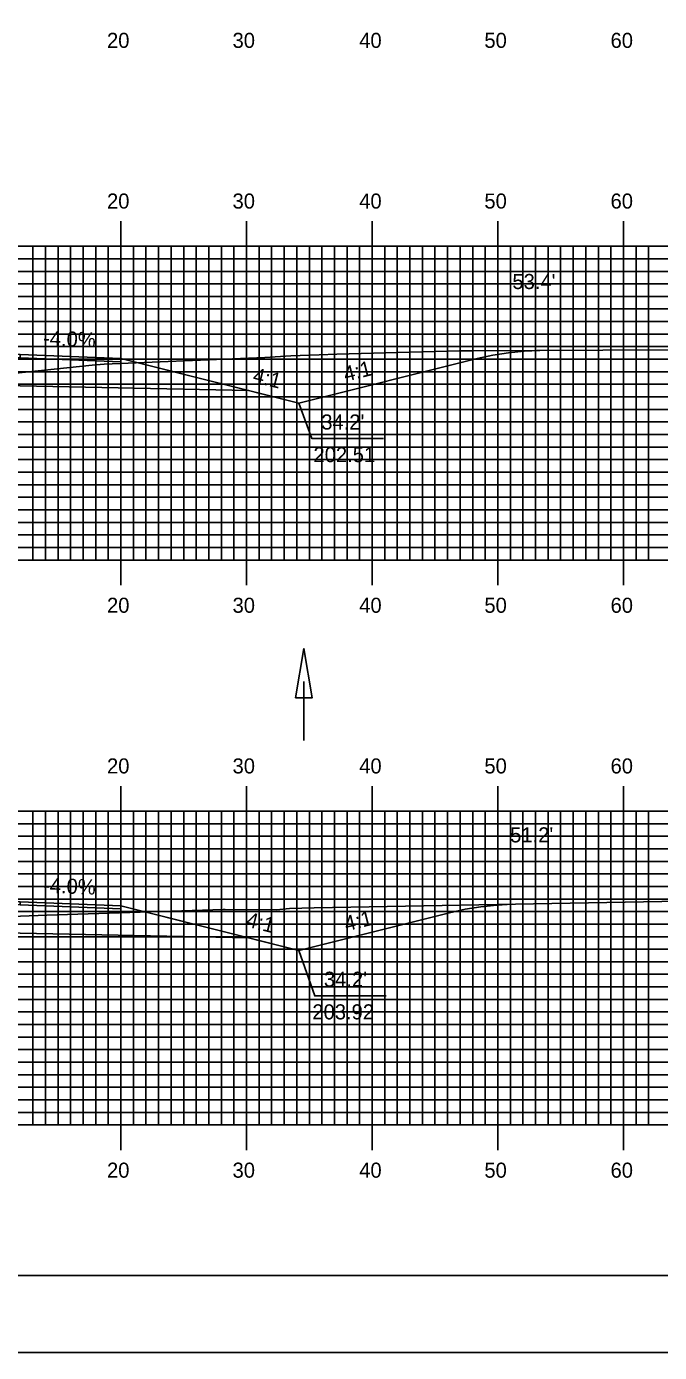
# Model space of a CAD drawing. Extents: x 1821998 to 1822342, y 442591 to 442811.
# Drawn here: x 1822176.8 to 1822227.1, y 442590.5 to 442696.2 of the extents above; entities that cross this region are included whole.
import ezdxf

# ---------------------------------------------------------------- set-up
doc = ezdxf.new("R2010")
doc.units = 0
for name, color, linetype in [('ANNOTATION', 7, 'Continuous'), ('BORDER', 7, 'Continuous'), ('D_Drainage_Ditch_Line', 7, 'Continuous'), ('D_Roadway_Centerline', 7, 'Continuous'), ('D_Roadway_Edge_Shoulder', 7, 'Continuous'), ('D_Roadway_SlopeLines', 7, 'Continuous'), ('D_Roadway_SubGrade', 7, 'Continuous'), ('D_Text_Standard', 7, 'Continuous'), ('H_V ANNOTATION', 7, 'Continuous'), ('MAJOR', 7, 'Continuous'), ('MINOR', 7, 'Continuous'), ('PLOT BOUNDARY', 7, 'Continuous'), ('S_Roadway_Centerline', 7, 'Continuous')]:
    doc.layers.add(name, color=color, linetype=linetype)

msp = doc.modelspace()

# ---------------------------------------------------------------- linework, layer by layer
at = {"layer": 'ANNOTATION'}
for points in [[(1822205.16, 442663.35), (1822199.47, 442663.35), (1822198.43, 442666.18)], [(1822205.38, 442618.95), (1822199.69, 442618.95), (1822198.43, 442622.58)]]:
    msp.add_lwpolyline(points, dxfattribs=at)
at = {"layer": 'BORDER'}
msp.add_lwpolyline([(1822014.66, 442596.67), (1822334.66, 442596.67), (1822334.66, 442806.67), (1822014.66, 442806.67)], close=True, dxfattribs=at)
at = {"layer": 'D_Drainage_Ditch_Line'}
msp.add_line((1822198.83, 442644), (1822198.83, 442639.3), dxfattribs=at)
msp.add_lwpolyline([(1822198.17, 442642.69), (1822199.48, 442642.69), (1822198.83, 442646.62)], close=True, dxfattribs=at)
at = {"layer": 'D_Roadway_Centerline'}
for points in [[(1822116.01, 442664.99), (1822122.31, 442666.56), (1822123.97, 442666.97), (1822134.31, 442669.56), (1822140.32, 442669.8), (1822164.26, 442670.28), (1822176.26, 442670.04), (1822184.26, 442669.72), (1822194.43, 442667.18), (1822198.43, 442666.18), (1822212.61, 442669.72), (1822213.86, 442669.99), (1822215.11, 442670.19), (1822216.36, 442670.31), (1822217.61, 442670.36)], [(1822113.09, 442620.68), (1822122.26, 442622.97), (1822123.91, 442623.38), (1822134.26, 442625.97), (1822140.26, 442626.21), (1822164.26, 442626.69), (1822176.26, 442626.45), (1822184.26, 442626.13), (1822194.43, 442623.58), (1822198.43, 442622.58), (1822210.42, 442625.58), (1822211.67, 442625.86), (1822212.92, 442626.06), (1822214.17, 442626.19), (1822215.42, 442626.25)]]:
    msp.add_lwpolyline(points, dxfattribs=at)
at = {"layer": 'D_Roadway_Edge_Shoulder'}
for points in [[(1822176.26, 442670.04), (1822184.26, 442669.72), (1822184.26, 442669.47), (1822176.26, 442669.79)], [(1822176.26, 442626.45), (1822184.26, 442626.13), (1822184.26, 442625.88), (1822176.26, 442626.2)]]:
    msp.add_lwpolyline(points, close=True, dxfattribs=at)
at = {"layer": 'D_Roadway_SlopeLines'}
for points in [[(1822198.43, 442666.18), (1822212.61, 442669.72), (1822213.86, 442669.99), (1822215.11, 442670.19), (1822216.36, 442670.31), (1822217.61, 442670.36)], [(1822184.26, 442669.72), (1822198.43, 442666.18)], [(1822184.26, 442626.13), (1822198.43, 442622.58)], [(1822198.43, 442622.58), (1822210.42, 442625.58), (1822211.67, 442625.86), (1822212.92, 442626.06), (1822214.17, 442626.19), (1822215.42, 442626.25)]]:
    msp.add_lwpolyline(points, dxfattribs=at)
at = {"layer": 'D_Roadway_SubGrade'}
for points in [[(1822140.32, 442667.3), (1822123.97, 442666.97), (1822134.31, 442669.56), (1822134.31, 442669.31), (1822140.32, 442669.55), (1822164.26, 442670.03), (1822176.26, 442669.79), (1822184.26, 442669.47), (1822184.26, 442669.72), (1822194.43, 442667.18), (1822176.26, 442667.54), (1822164.26, 442667.78)], [(1822140.26, 442623.71), (1822123.91, 442623.38), (1822134.26, 442625.97), (1822134.26, 442625.72), (1822140.26, 442625.96), (1822164.26, 442626.44), (1822176.26, 442626.2), (1822184.26, 442625.88), (1822184.26, 442626.13), (1822194.43, 442623.58), (1822176.26, 442623.95), (1822164.26, 442624.19)]]:
    msp.add_lwpolyline(points, close=True, dxfattribs=at)
at = {"layer": 'MAJOR'}
for p, q in [((1822184.26, 442680.67), (1822184.26, 442678.67)), ((1822194.26, 442680.67), (1822194.26, 442678.67)), ((1822204.26, 442680.67), (1822204.26, 442678.67)), ((1822214.26, 442680.67), (1822214.26, 442678.67)), ((1822224.26, 442680.67), (1822224.26, 442678.67)), ((1822024.26, 442678.67), (1822304.26, 442678.67)), ((1822024.26, 442678.67), (1822304.26, 442678.67)), ((1822184.26, 442653.67), (1822184.26, 442678.67)), ((1822194.26, 442653.67), (1822194.26, 442678.67)), ((1822204.26, 442653.67), (1822204.26, 442678.67)), ((1822214.26, 442653.67), (1822214.26, 442678.67)), ((1822224.26, 442653.67), (1822224.26, 442678.67)), ((1822024.26, 442673.67), (1822304.26, 442673.67)), ((1822024.26, 442668.67), (1822304.26, 442668.67)), ((1822024.26, 442663.67), (1822304.26, 442663.67)), ((1822024.26, 442658.67), (1822304.26, 442658.67)), ((1822024.26, 442653.67), (1822304.26, 442653.67)), ((1822024.26, 442653.67), (1822304.26, 442653.67)), ((1822184.26, 442651.66), (1822184.26, 442653.67)), ((1822194.26, 442651.66), (1822194.26, 442653.67)), ((1822204.26, 442651.66), (1822204.26, 442653.67)), ((1822214.26, 442651.66), (1822214.26, 442653.67)), ((1822224.26, 442651.66), (1822224.26, 442653.67)), ((1822184.26, 442635.67), (1822184.26, 442633.67)), ((1822194.26, 442635.67), (1822194.26, 442633.67)), ((1822204.26, 442635.67), (1822204.26, 442633.67)), ((1822214.26, 442635.67), (1822214.26, 442633.67)), ((1822224.26, 442635.67), (1822224.26, 442633.67)), ((1822024.26, 442633.67), (1822304.26, 442633.67)), ((1822024.26, 442633.67), (1822304.26, 442633.67)), ((1822184.26, 442608.67), (1822184.26, 442633.67)), ((1822194.26, 442608.67), (1822194.26, 442633.67)), ((1822204.26, 442608.67), (1822204.26, 442633.67)), ((1822214.26, 442608.67), (1822214.26, 442633.67)), ((1822224.26, 442608.67), (1822224.26, 442633.67)), ((1822024.26, 442628.67), (1822304.26, 442628.67)), ((1822024.26, 442623.67), (1822304.26, 442623.67)), ((1822024.26, 442618.67), (1822304.26, 442618.67)), ((1822024.26, 442613.67), (1822304.26, 442613.67)), ((1822024.26, 442608.67), (1822304.26, 442608.67)), ((1822024.26, 442608.67), (1822304.26, 442608.67)), ((1822184.26, 442606.66), (1822184.26, 442608.67)), ((1822194.26, 442606.66), (1822194.26, 442608.67)), ((1822204.26, 442606.66), (1822204.26, 442608.67)), ((1822214.26, 442606.66), (1822214.26, 442608.67)), ((1822224.26, 442606.66), (1822224.26, 442608.67))]:
    msp.add_line(p, q, dxfattribs=at)
at = {"layer": 'MINOR'}
for p, q in [((1822177.26, 442653.67), (1822177.26, 442678.67)), ((1822178.26, 442653.67), (1822178.26, 442678.67)), ((1822179.26, 442653.67), (1822179.26, 442678.67)), ((1822180.26, 442653.67), (1822180.26, 442678.67)), ((1822181.26, 442653.67), (1822181.26, 442678.67)), ((1822182.26, 442653.67), (1822182.26, 442678.67)), ((1822183.26, 442653.67), (1822183.26, 442678.67)), ((1822185.26, 442653.67), (1822185.26, 442678.67)), ((1822186.26, 442653.67), (1822186.26, 442678.67)), ((1822187.26, 442653.67), (1822187.26, 442678.67)), ((1822188.26, 442653.67), (1822188.26, 442678.67)), ((1822189.26, 442653.67), (1822189.26, 442678.67)), ((1822190.26, 442653.67), (1822190.26, 442678.67)), ((1822191.26, 442653.67), (1822191.26, 442678.67)), ((1822192.26, 442653.67), (1822192.26, 442678.67)), ((1822193.26, 442653.67), (1822193.26, 442678.67)), ((1822195.26, 442653.67), (1822195.26, 442678.67)), ((1822196.26, 442653.67), (1822196.26, 442678.67)), ((1822197.26, 442653.67), (1822197.26, 442678.67)), ((1822198.26, 442653.67), (1822198.26, 442678.67)), ((1822199.26, 442653.67), (1822199.26, 442678.67)), ((1822200.26, 442653.67), (1822200.26, 442678.67)), ((1822201.26, 442653.67), (1822201.26, 442678.67)), ((1822202.26, 442653.67), (1822202.26, 442678.67)), ((1822203.26, 442653.67), (1822203.26, 442678.67)), ((1822205.26, 442653.67), (1822205.26, 442678.67)), ((1822206.26, 442653.67), (1822206.26, 442678.67)), ((1822207.26, 442653.67), (1822207.26, 442678.67)), ((1822208.26, 442653.67), (1822208.26, 442678.67)), ((1822209.26, 442653.67), (1822209.26, 442678.67)), ((1822210.26, 442653.67), (1822210.26, 442678.67)), ((1822211.26, 442653.67), (1822211.26, 442678.67)), ((1822212.26, 442653.67), (1822212.26, 442678.67)), ((1822213.26, 442653.67), (1822213.26, 442678.67)), ((1822215.26, 442653.67), (1822215.26, 442678.67)), ((1822216.26, 442653.67), (1822216.26, 442678.67)), ((1822217.26, 442653.67), (1822217.26, 442678.67)), ((1822218.26, 442653.67), (1822218.26, 442678.67)), ((1822219.26, 442653.67), (1822219.26, 442678.67)), ((1822220.26, 442653.67), (1822220.26, 442678.67)), ((1822221.26, 442653.67), (1822221.26, 442678.67)), ((1822222.26, 442653.67), (1822222.26, 442678.67)), ((1822223.26, 442653.67), (1822223.26, 442678.67)), ((1822225.26, 442653.67), (1822225.26, 442678.67)), ((1822226.26, 442653.67), (1822226.26, 442678.67)), ((1822024.26, 442677.67), (1822304.26, 442677.67)), ((1822024.26, 442676.67), (1822304.26, 442676.67)), ((1822024.26, 442675.67), (1822304.26, 442675.67)), ((1822024.26, 442674.67), (1822304.26, 442674.67)), ((1822024.26, 442672.67), (1822304.26, 442672.67)), ((1822024.26, 442671.67), (1822304.26, 442671.67)), ((1822024.26, 442670.67), (1822304.26, 442670.67)), ((1822024.26, 442669.67), (1822304.26, 442669.67)), ((1822024.26, 442667.67), (1822304.26, 442667.67)), ((1822024.26, 442666.67), (1822304.26, 442666.67)), ((1822024.26, 442665.67), (1822304.26, 442665.67)), ((1822024.26, 442664.67), (1822304.26, 442664.67)), ((1822024.26, 442662.67), (1822304.26, 442662.67)), ((1822024.26, 442661.67), (1822304.26, 442661.67)), ((1822024.26, 442660.67), (1822304.26, 442660.67)), ((1822024.26, 442659.67), (1822304.26, 442659.67)), ((1822024.26, 442657.67), (1822304.26, 442657.67)), ((1822024.26, 442656.67), (1822304.26, 442656.67)), ((1822024.26, 442655.67), (1822304.26, 442655.67)), ((1822024.26, 442654.67), (1822304.26, 442654.67)), ((1822177.26, 442608.67), (1822177.26, 442633.67)), ((1822178.26, 442608.67), (1822178.26, 442633.67)), ((1822179.26, 442608.67), (1822179.26, 442633.67)), ((1822180.26, 442608.67), (1822180.26, 442633.67)), ((1822181.26, 442608.67), (1822181.26, 442633.67)), ((1822182.26, 442608.67), (1822182.26, 442633.67)), ((1822183.26, 442608.67), (1822183.26, 442633.67)), ((1822185.26, 442608.67), (1822185.26, 442633.67)), ((1822186.26, 442608.67), (1822186.26, 442633.67)), ((1822187.26, 442608.67), (1822187.26, 442633.67)), ((1822188.26, 442608.67), (1822188.26, 442633.67)), ((1822189.26, 442608.67), (1822189.26, 442633.67)), ((1822190.26, 442608.67), (1822190.26, 442633.67)), ((1822191.26, 442608.67), (1822191.26, 442633.67)), ((1822192.26, 442608.67), (1822192.26, 442633.67)), ((1822193.26, 442608.67), (1822193.26, 442633.67)), ((1822195.26, 442608.67), (1822195.26, 442633.67)), ((1822196.26, 442608.67), (1822196.26, 442633.67)), ((1822197.26, 442608.67), (1822197.26, 442633.67)), ((1822198.26, 442608.67), (1822198.26, 442633.67)), ((1822199.26, 442608.67), (1822199.26, 442633.67)), ((1822200.26, 442608.67), (1822200.26, 442633.67)), ((1822201.26, 442608.67), (1822201.26, 442633.67)), ((1822202.26, 442608.67), (1822202.26, 442633.67)), ((1822203.26, 442608.67), (1822203.26, 442633.67)), ((1822205.26, 442608.67), (1822205.26, 442633.67)), ((1822206.26, 442608.67), (1822206.26, 442633.67)), ((1822207.26, 442608.67), (1822207.26, 442633.67)), ((1822208.26, 442608.67), (1822208.26, 442633.67)), ((1822209.26, 442608.67), (1822209.26, 442633.67)), ((1822210.26, 442608.67), (1822210.26, 442633.67)), ((1822211.26, 442608.67), (1822211.26, 442633.67)), ((1822212.26, 442608.67), (1822212.26, 442633.67)), ((1822213.26, 442608.67), (1822213.26, 442633.67)), ((1822215.26, 442608.67), (1822215.26, 442633.67)), ((1822216.26, 442608.67), (1822216.26, 442633.67)), ((1822217.26, 442608.67), (1822217.26, 442633.67)), ((1822218.26, 442608.67), (1822218.26, 442633.67)), ((1822219.26, 442608.67), (1822219.26, 442633.67)), ((1822220.26, 442608.67), (1822220.26, 442633.67)), ((1822221.26, 442608.67), (1822221.26, 442633.67)), ((1822222.26, 442608.67), (1822222.26, 442633.67)), ((1822223.26, 442608.67), (1822223.26, 442633.67)), ((1822225.26, 442608.67), (1822225.26, 442633.67)), ((1822226.26, 442608.67), (1822226.26, 442633.67)), ((1822024.26, 442632.67), (1822304.26, 442632.67)), ((1822024.26, 442631.67), (1822304.26, 442631.67)), ((1822024.26, 442630.67), (1822304.26, 442630.67)), ((1822024.26, 442629.67), (1822304.26, 442629.67)), ((1822024.26, 442627.67), (1822304.26, 442627.67)), ((1822024.26, 442626.67), (1822304.26, 442626.67)), ((1822024.26, 442625.67), (1822304.26, 442625.67)), ((1822024.26, 442624.67), (1822304.26, 442624.67)), ((1822024.26, 442622.67), (1822304.26, 442622.67)), ((1822024.26, 442621.67), (1822304.26, 442621.67)), ((1822024.26, 442620.67), (1822304.26, 442620.67)), ((1822024.26, 442619.67), (1822304.26, 442619.67)), ((1822024.26, 442617.67), (1822304.26, 442617.67)), ((1822024.26, 442616.67), (1822304.26, 442616.67)), ((1822024.26, 442615.67), (1822304.26, 442615.67)), ((1822024.26, 442614.67), (1822304.26, 442614.67)), ((1822024.26, 442612.67), (1822304.26, 442612.67)), ((1822024.26, 442611.67), (1822304.26, 442611.67)), ((1822024.26, 442610.67), (1822304.26, 442610.67)), ((1822024.26, 442609.67), (1822304.26, 442609.67))]:
    msp.add_line(p, q, dxfattribs=at)
at = {"layer": 'PLOT BOUNDARY'}
msp.add_lwpolyline([(1821998.47, 442590.55), (1822338.47, 442590.55), (1822338.47, 442810.55), (1821998.47, 442810.55)], close=True, dxfattribs=at)
at = {"layer": 'S_Roadway_Centerline'}
for points in [[(1822094.4, 442663.34), (1822107.97, 442665.29), (1822112.21, 442664.95), (1822113.29, 442664.81), (1822115.6, 442664.96), (1822131.19, 442666.05), (1822133.36, 442665.98), (1822137.3, 442666.07), (1822144.39, 442666.1), (1822149.35, 442666.24), (1822156.74, 442666.89), (1822164.97, 442667.3), (1822168.56, 442667.8), (1822181.97, 442669.2), (1822182.92, 442669.27), (1822194.41, 442669.75), (1822195.72, 442669.8), (1822197.79, 442669.93), (1822200.03, 442670.01), (1822201.44, 442670.06), (1822211.18, 442670.35), (1822212.28, 442670.33), (1822217.36, 442670.36), (1822227.86, 442670.42)], [(1822093.73, 442620.12), (1822106.05, 442620.56), (1822110.36, 442620.63), (1822121.91, 442620.83), (1822126.17, 442620.88), (1822127.37, 442620.92), (1822139.74, 442621.73), (1822144.22, 442621.87), (1822153.29, 442623.31), (1822161.39, 442624.49), (1822164.73, 442624.84), (1822165.34, 442624.89), (1822171.4, 442625.14), (1822174.88, 442625.26), (1822178.36, 442625.37), (1822192.4, 442625.83), (1822192.5, 442625.83), (1822192.55, 442625.84), (1822192.56, 442625.84), (1822196.65, 442625.82), (1822197.68, 442625.91), (1822199.65, 442625.97), (1822233.12, 442626.58)]]:
    msp.add_lwpolyline(points, dxfattribs=at)

# ---------------------------------------------------------------- texts
at = {"layer": 'ANNOTATION'}
for s, rotation, p in [('-4.0%', 357.7094, (1822178.05, 442670.77)), ('4:1', 14.0362, (1822202.15, 442667.87)), ('4:1', 345.9638, (1822194.69, 442667.86)), ('-4.0%', 357.7094, (1822178.05, 442627.18)), ('4:1', 14.0362, (1822202.21, 442624.09)), ('4:1', 345.9638, (1822194.16, 442624.49))]:
    msp.add_text(s, height=1.2, rotation=rotation, dxfattribs=at).set_placement(p)
for s, p in [("34.2'", (1822200.21, 442664.07)), ('202.51', (1822199.59, 442661.47)), ("34.2'", (1822200.42, 442619.68)), ('203.92', (1822199.5, 442617.08))]:
    msp.add_text(s, height=1.2, dxfattribs=at).set_placement(p)
at = {"layer": 'D_Text_Standard'}
for s, p in [("53.4'", (1822215.42, 442675.26)), ("51.2'", (1822215.24, 442631.18))]:
    msp.add_text(s, height=1.2, dxfattribs=at).set_placement(p)
at = {"layer": 'H_V ANNOTATION'}
for s, p in [('20', (1822183.16, 442694.47)), ('30', (1822193.15, 442694.47)), ('40', (1822203.23, 442694.47)), ('50', (1822213.19, 442694.47)), ('60', (1822223.23, 442694.47)), ('20', (1822183.16, 442681.67)), ('30', (1822193.15, 442681.67)), ('40', (1822203.23, 442681.67)), ('50', (1822213.19, 442681.67)), ('60', (1822223.23, 442681.67)), ('20', (1822183.16, 442649.47)), ('30', (1822193.15, 442649.47)), ('40', (1822203.23, 442649.47)), ('50', (1822213.19, 442649.47)), ('60', (1822223.23, 442649.47)), ('20', (1822183.16, 442636.67)), ('30', (1822193.15, 442636.67)), ('40', (1822203.23, 442636.67)), ('50', (1822213.19, 442636.67)), ('60', (1822223.23, 442636.67)), ('20', (1822183.16, 442604.47)), ('30', (1822193.15, 442604.47)), ('40', (1822203.23, 442604.47)), ('50', (1822213.19, 442604.47)), ('60', (1822223.23, 442604.47))]:
    msp.add_text(s, height=1.2, dxfattribs=at).set_placement(p)

doc.saveas('drawing.dxf')
